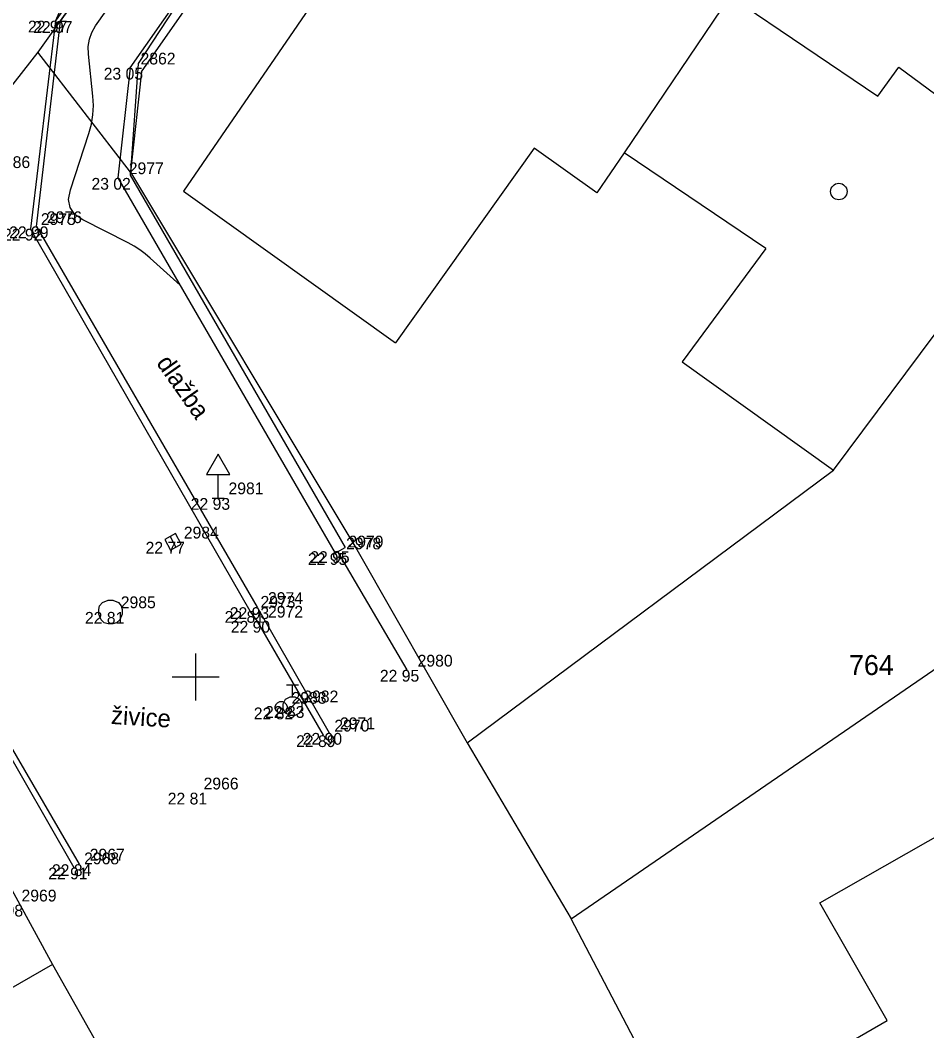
# Model space of a CAD drawing. Extents: x -702257 to -701487, y -1009871 to -1008841.
# Drawn here: x -701878.73 to -701859.46, y -1009582.52 to -1009561.05 of the extents above; entities that cross this region are included whole.
import ezdxf

# ---------------------------------------------------------------- set-up
doc = ezdxf.new("R2010")
doc.units = 0
for name, color, linetype in [('Ex_Major Contours', 7, 'Continuous'), ('Z_body', 7, 'Continuous'), ('Z_body_cisla', 7, 'Continuous'), ('Z_body_vysky_redukovane', 7, 'Continuous'), ('Z_dopravni_znacky', 7, 'Continuous'), ('Z_hektometricka_sit', 7, 'Continuous'), ('Z_katastr_cisla_pozemkova', 7, 'Continuous'), ('Z_katastr_hranice', 7, 'Continuous'), ('Z_katastr_vnitrni_kresba', 7, 'Continuous'), ('Z_katastr_znacky_budov', 7, 'Continuous'), ('Z_komunikace', 7, 'Continuous'), ('Z_obruba', 7, 'Continuous'), ('Z_ploty', 7, 'Continuous'), ('Z_popisy', 7, 'Continuous'), ('Z_site_kanalizace_znaky', 7, 'Continuous'), ('Z_site_vodovod_znaky', 7, 'Continuous'), ('Z_vstupy', 7, 'Continuous')]:
    doc.layers.add(name, color=color, linetype=linetype)

# ---------------------------------------------------------------- blocks, each defined once
blk = doc.blocks.new('POINT_DISPLAY')
blk.add_line((0, 0), (0, 0))
blk = doc.blocks.new('Z620')
for p, q in [((-0.17, 0.2), (-0.05, 0.25)), ((-0.05, 0.25), (0.05, 0.25)), ((0.05, 0.25), (0.17, 0.2)), ((-0.25, 0.05), (-0.23, 0.13)), ((-0.25, -0.05), (-0.25, 0.05)), ((-0.23, 0.13), (-0.17, 0.2)), ((0.17, 0.2), (0.23, 0.13)), ((0.23, 0.13), (0.25, 0.05)), ((0.25, 0.05), (0.25, -0.05)), ((-0.2, -0.17), (-0.25, -0.05)), ((-0.13, -0.23), (-0.2, -0.17)), ((0.2, -0.17), (0.13, -0.23)), ((0.25, -0.05), (0.2, -0.17)), ((-0.05, -0.25), (-0.13, -0.23)), ((0.05, -0.25), (-0.05, -0.25)), ((0.13, -0.23), (0.05, -0.25))]:
    blk.add_line(p, q)
blk = doc.blocks.new('Z46260')
for p, q in [((0.13, 0.13), (-0.13, 0.13)), ((-0.13, 0.13), (-0.13, -0.13)), ((0.13, 0), (-0.13, 0)), ((0.13, -0.13), (0.13, 0.13)), ((-0.13, -0.13), (0.13, -0.13))]:
    blk.add_line(p, q)
blk = doc.blocks.new('Z18')
for p, q in [((-0.13, 0.45), (0.13, 0.45)), ((0, 0.2), (0, 0.45)), ((-0.2, 0.05), (-0.15, 0.15)), ((-0.2, -0.05), (-0.2, 0.05)), ((-0.15, 0.15), (-0.05, 0.2)), ((0.15, 0.15), (-0.15, -0.15)), ((-0.05, 0.2), (0.05, 0.2)), ((0.05, 0.2), (0.15, 0.15)), ((0.15, 0.15), (0.2, 0.05)), ((0.2, 0.05), (0.2, -0.05)), ((-0.15, -0.15), (-0.2, -0.05)), ((-0.05, -0.2), (-0.15, -0.15)), ((0.05, -0.2), (-0.05, -0.2)), ((0.15, -0.15), (0.05, -0.2)), ((0.2, -0.05), (0.15, -0.15))]:
    blk.add_line(p, q)
blk = doc.blocks.new('Z614')
for p, q in [((-0.13, 0.03), (-0.1, 0.08)), ((-0.13, -0.03), (-0.13, 0.03)), ((-0.1, 0.08), (-0.08, 0.1)), ((-0.08, 0.1), (-0.03, 0.13)), ((-0.03, 0.13), (0.03, 0.13)), ((0.03, 0.13), (0.08, 0.1)), ((0.08, 0.1), (0.1, 0.08)), ((0.1, 0.08), (0.13, 0.03)), ((0.13, 0.03), (0.13, -0.03)), ((-0.1, -0.08), (-0.13, -0.03)), ((-0.08, -0.1), (-0.1, -0.08)), ((-0.03, -0.13), (-0.08, -0.1)), ((0.03, -0.13), (-0.03, -0.13)), ((0.08, -0.1), (0.03, -0.13)), ((0.1, -0.08), (0.08, -0.1)), ((0.13, -0.03), (0.1, -0.08))]:
    blk.add_line(p, q)
blk = doc.blocks.new('Z527')
for p, q in [((0, 0.93), (-0.25, 0.5)), ((0.25, 0.5), (0, 0.93)), ((-0.25, 0.5), (0.25, 0.5)), ((0, 0), (0, 0.5)), ((-0.13, 0), (0.13, 0))]:
    blk.add_line(p, q)

msp = doc.modelspace()

# ---------------------------------------------------------------- linework, layer by layer
at = {"layer": 'Ex_Major Contours'}
msp.add_lwpolyline([(-701875.33, -1009566.677), (-701875.965, -1009566.103), (-701876.074, -1009566.011), (-701876.187, -1009565.927), (-701876.307, -1009565.85), (-701876.431, -1009565.782), (-701877.397, -1009565.293), (-701877.566, -1009565.176), (-701877.666, -1009565.03), (-701877.698, -1009564.856), (-701877.661, -1009564.654), (-701877.266, -1009563.457), (-701877.213, -1009563.261), (-701877.181, -1009563.063), (-701877.171, -1009562.864), (-701877.182, -1009562.661), (-701877.279, -1009561.773), (-701877.283, -1009561.611), (-701877.258, -1009561.456), (-701877.205, -1009561.308), (-701877.124, -1009561.168), (-701876.711, -1009560.577)], dxfattribs=at)
at = {"layer": 'Z_hektometricka_sit'}
for p, q in [((-701875, -1009574.5), (-701875, -1009575.5)), ((-701875, -1009574.5), (-701875, -1009575.5)), ((-701875.5, -1009575), (-701874.5, -1009575)), ((-701875.5, -1009575), (-701874.5, -1009575))]:
    msp.add_line(p, q, dxfattribs=at)
at = {"layer": 'Z_katastr_hranice'}
for p, q in [((-701769.49, -1009408.19), (-701878.35, -1009561.73)), ((-701874.31, -1009559.05), (-701876.22, -1009561.97)), ((-701878.35, -1009561.73), (-701879.2, -1009562.8)), ((-701876.38, -1009564.28), (-701878.35, -1009561.73)), ((-701876.22, -1009561.97), (-701876.38, -1009564.28)), ((-701876.38, -1009564.28), (-701871.57, -1009572.29)), ((-701861.44, -1009570.61), (-701858.61, -1009566.81)), ((-701869.23, -1009576.4), (-701861.44, -1009570.61)), ((-701867.02, -1009580.14), (-701855.2, -1009572.03)), ((-701871.57, -1009572.29), (-701869.23, -1009576.4)), ((-701869.23, -1009576.4), (-701867.02, -1009580.14)), ((-701880.43, -1009576.74), (-701878.04, -1009581.11)), ((-701864.59, -1009584.76), (-701867.02, -1009580.14)), ((-701878.04, -1009581.11), (-701888.78, -1009587.24)), ((-701878.04, -1009581.11), (-701875.98, -1009584.76))]:
    msp.add_line(p, q, dxfattribs=at)
at = {"layer": 'Z_katastr_vnitrni_kresba'}
for p, q in [((-701872.35, -1009560.45), (-701875.26, -1009564.68)), ((-701863.64, -1009560.54), (-701865.89, -1009563.87)), ((-701863.64, -1009560.54), (-701860.5, -1009562.66)), ((-701860.5, -1009562.66), (-701860.05, -1009562.05)), ((-701860.05, -1009562.05), (-701856.83, -1009564.42)), ((-701867.8, -1009563.77), (-701870.75, -1009567.9)), ((-701866.47, -1009564.72), (-701867.8, -1009563.77)), ((-701865.89, -1009563.87), (-701866.47, -1009564.72)), ((-701862.88, -1009565.9), (-701865.89, -1009563.87)), ((-701875.26, -1009564.68), (-701870.75, -1009567.9)), ((-701862.88, -1009565.9), (-701864.66, -1009568.31)), ((-701864.66, -1009568.31), (-701861.44, -1009570.61)), ((-701861.73, -1009579.8), (-701854.97, -1009575.94)), ((-701860.3, -1009582.3), (-701861.73, -1009579.8)), ((-701864.59, -1009584.76), (-701860.3, -1009582.3))]:
    msp.add_line(p, q, dxfattribs=at)
at = {"layer": 'Z_katastr_znacky_budov'}
msp.add_circle((-701861.327, -1009564.689), 0.175, dxfattribs=at)
at = {"layer": 'Z_komunikace'}
for p, q in [((-701877.86, -1009560.79), (-701877.98, -1009561.06)), ((-701877.98, -1009561.06), (-701878.51, -1009565.48)), ((-701873.84, -1009573.6), (-701878.51, -1009565.48)), ((-701872.28, -1009576.24), (-701873.69, -1009573.81)), ((-701877.47, -1009578.98), (-701879.72, -1009575.11))]:
    msp.add_line(p, q, dxfattribs=at)
at = {"layer": 'Z_obruba'}
for p, q in [((-701875.79, -1009557.93), (-701877.98, -1009561.06)), ((-701877.87, -1009561.07), (-701875.68, -1009557.99)), ((-701878.38, -1009565.43), (-701877.87, -1009561.07)), ((-701878.38, -1009565.43), (-701873.69, -1009573.52)), ((-701873.69, -1009573.81), (-701873.84, -1009573.6)), ((-701873.69, -1009573.52), (-701872.16, -1009576.19)), ((-701879.78, -1009575.23), (-701877.59, -1009579.05))]:
    msp.add_line(p, q, dxfattribs=at)
at = {"layer": 'Z_ploty'}
for p, q in [((-701876.39, -1009562.06), (-701874.35, -1009559.14)), ((-701876.15, -1009562.15), (-701874.15, -1009559.29)), ((-701876.39, -1009562.06), (-701876.65, -1009564.4)), ((-701876.15, -1009562.15), (-701876.39, -1009564.34)), ((-701876.65, -1009564.4), (-701872.03, -1009572.37)), ((-701876.39, -1009564.34), (-701871.82, -1009572.25)), ((-701872.03, -1009572.37), (-701871.82, -1009572.25))]:
    msp.add_line(p, q, dxfattribs=at)
at = {"layer": 'Z_vstupy'}
msp.add_line((-701870.5, -1009574.85), (-701871.98, -1009572.33), dxfattribs=at)

# ---------------------------------------------------------------- block references
at = {"layer": 'Z_body'}
for p in [(-701877.98, -1009561.06), (-701877.87, -1009561.07), (-701876.39, -1009562.06), (-701876.65, -1009564.4), (-701878.38, -1009565.43), (-701878.51, -1009565.48), (-701874.52, -1009571.2), (-701875.48, -1009572.13), (-701871.98, -1009572.33), (-701872.03, -1009572.37), (-701876.81, -1009573.62), (-701873.84, -1009573.6), (-701873.69, -1009573.52), (-701873.69, -1009573.81), (-701870.5, -1009574.85), (-701873.18, -1009575.65), (-701872.94, -1009575.62), (-701872.16, -1009576.19), (-701872.28, -1009576.24), (-701875.05, -1009577.46), (-701877.47, -1009578.98), (-701877.59, -1009579.05)]:
    msp.add_blockref('POINT_DISPLAY', p, dxfattribs=at)
at = {"layer": 'Z_dopravni_znacky'}
msp.add_blockref('Z527', (-701874.52, -1009571.2), dxfattribs=at)
at = {"layer": 'Z_site_kanalizace_znaky', "rotation": 118.79999999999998}
msp.add_blockref('Z46260', (-701875.48, -1009572.13), dxfattribs=at)
at = {"layer": 'Z_site_kanalizace_znaky'}
msp.add_blockref('Z620', (-701876.81, -1009573.62), dxfattribs=at)
at = {"layer": 'Z_site_vodovod_znaky'}
for name, p in [('Z18', (-701872.94, -1009575.62)), ('Z614', (-701873.18, -1009575.65))]:
    msp.add_blockref(name, p, dxfattribs=at)

# ---------------------------------------------------------------- texts
at = {"layer": 'Z_body_cisla'}
for s, p in [('2862', (-701876.17, -1009561.99)), ('2986', (-701879.26, -1009564.19)), ('2977', (-701876.42, -1009564.32)), ('2975', (-701878.29, -1009565.4)), ('2976', (-701878.16, -1009565.36)), ('2981', (-701874.3, -1009571.12)), ('2984', (-701875.25, -1009572.06)), ('2978', (-701871.8, -1009572.29)), ('2979', (-701871.75, -1009572.25)), ('2974', (-701873.46, -1009573.45)), ('2985', (-701876.59, -1009573.54)), ('2973', (-701873.62, -1009573.53)), ('2972', (-701873.46, -1009573.74)), ('2980', (-701870.28, -1009574.78)), ('2983', (-701872.96, -1009575.57)), ('2982', (-701872.71, -1009575.54)), ('2970', (-701872.05, -1009576.16)), ('2971', (-701871.93, -1009576.11)), ('2966', (-701874.83, -1009577.39)), ('2968', (-701877.37, -1009578.98)), ('2967', (-701877.25, -1009578.9)), ('2969', (-701878.7, -1009579.77))]:
    msp.add_text(s, height=0.25, dxfattribs=at).set_placement(p)
at = {"layer": 'Z_body_vysky_redukovane'}
for s, p in [('22 97', (-701878.563, -1009561.31)), ('22 97', (-701878.453, -1009561.32)), ('23 05', (-701876.953, -1009562.31)), ('23 02', (-701877.213, -1009564.65)), ('22 99', (-701878.963, -1009565.68)), ('22 92', (-701879.093, -1009565.73)), ('22 93', (-701875.103, -1009571.45)), ('22 77', (-701876.063, -1009572.38)), ('22 95', (-701872.563, -1009572.58)), ('22 95', (-701872.613, -1009572.62)), ('22 81', (-701877.352, -1009573.87)), ('22 81', (-701874.382, -1009573.85)), ('22 93', (-701874.273, -1009573.77)), ('22 90', (-701874.252, -1009574.06)), ('22 95', (-701871.083, -1009575.1)), ('22 82', (-701873.763, -1009575.9)), ('22 83', (-701873.523, -1009575.87)), ('22 90', (-701872.723, -1009576.44)), ('22 89', (-701872.863, -1009576.49)), ('22 81', (-701875.592, -1009577.71)), ('22 84', (-701878.053, -1009579.23)), ('22 91', (-701878.132, -1009579.3)), ('22 98', (-701879.503, -1009580.09))]:
    msp.add_text(s, height=0.25, dxfattribs=at).set_placement(p)
at = {"layer": 'Z_katastr_cisla_pozemkova'}
msp.add_text('764', height=0.425, dxfattribs=at).set_placement((-701861.109, -1009574.96))
at = {"layer": 'Z_popisy'}
for s, rotation, p in [('dlažba', 305.1, (-701875.848, -1009568.332)), ('živice', 356.4, (-701876.806, -1009575.998))]:
    msp.add_text(s, height=0.38, rotation=rotation, dxfattribs=at).set_placement(p)

doc.saveas('drawing.dxf')
